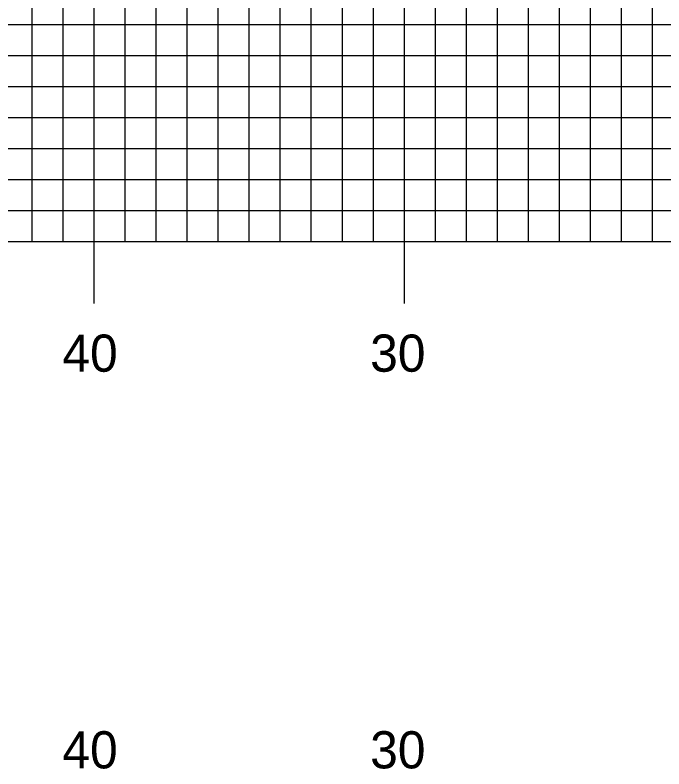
# Model space of a CAD drawing. Extents: x 1755888 to 1756232, y 442591 to 442811.
# Drawn here: x 1756011.5 to 1756032.43, y 442651.65 to 442675.97 of the extents above; entities that cross this region are included whole.
import ezdxf

# ---------------------------------------------------------------- set-up
doc = ezdxf.new("R2010")
doc.units = 0
for name, color, linetype in [('H_V ANNOTATION', 7, 'Continuous'), ('MAJOR', 7, 'Continuous'), ('MINOR', 7, 'Continuous')]:
    doc.layers.add(name, color=color, linetype=linetype)

msp = doc.modelspace()

# ---------------------------------------------------------------- linework, layer by layer
at = {"layer": 'MAJOR'}
for p, q in [((1756014.057, 442668.665), (1756014.057, 442703.665)), ((1756024.057, 442668.665), (1756024.057, 442703.665)), ((1755914.057, 442673.665), (1756194.057, 442673.665)), ((1755914.057, 442668.665), (1756194.057, 442668.665)), ((1755914.057, 442668.665), (1756194.057, 442668.665)), ((1756014.057, 442666.661), (1756014.057, 442668.665)), ((1756024.057, 442666.661), (1756024.057, 442668.665))]:
    msp.add_line(p, q, dxfattribs=at)
at = {"layer": 'MINOR'}
for p, q in [((1756012.057, 442668.665), (1756012.057, 442703.665)), ((1756013.057, 442668.665), (1756013.057, 442703.665)), ((1756015.057, 442668.665), (1756015.057, 442703.665)), ((1756016.057, 442668.665), (1756016.057, 442703.665)), ((1756017.057, 442668.665), (1756017.057, 442703.665)), ((1756018.057, 442668.665), (1756018.057, 442703.665)), ((1756019.057, 442668.665), (1756019.057, 442703.665)), ((1756020.057, 442668.665), (1756020.057, 442703.665)), ((1756021.057, 442668.665), (1756021.057, 442703.665)), ((1756022.057, 442668.665), (1756022.057, 442703.665)), ((1756023.057, 442668.665), (1756023.057, 442703.665)), ((1756025.057, 442668.665), (1756025.057, 442703.665)), ((1756026.057, 442668.665), (1756026.057, 442703.665)), ((1756027.057, 442668.665), (1756027.057, 442703.665)), ((1756028.057, 442668.665), (1756028.057, 442703.665)), ((1756029.057, 442668.665), (1756029.057, 442703.665)), ((1756030.057, 442668.665), (1756030.057, 442703.665)), ((1756031.057, 442668.665), (1756031.057, 442703.665)), ((1756032.057, 442668.665), (1756032.057, 442703.665)), ((1755914.057, 442675.665), (1756194.057, 442675.665)), ((1755914.057, 442674.665), (1756194.057, 442674.665)), ((1755914.057, 442672.665), (1756194.057, 442672.665)), ((1755914.057, 442671.665), (1756194.057, 442671.665)), ((1755914.057, 442670.665), (1756194.057, 442670.665)), ((1755914.057, 442669.665), (1756194.057, 442669.665))]:
    msp.add_line(p, q, dxfattribs=at)

# ---------------------------------------------------------------- texts
at = {"layer": 'H_V ANNOTATION'}
for s, p in [('40', (1756013.029, 442664.465)), ('30', (1756022.954, 442664.465)), ('40', (1756013.029, 442651.665)), ('30', (1756022.954, 442651.665))]:
    msp.add_text(s, height=1.2, dxfattribs=at).set_placement(p)

doc.saveas('drawing.dxf')
